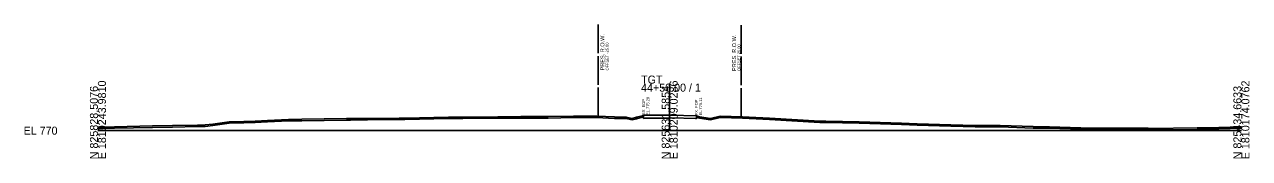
# Model space of a CAD drawing. Extents: x -26 to 1855242, y -29 to 826069.
# Drawn here: x -25.7 to 402.8, y 12490.3 to 12537 of the extents above; entities that cross this region are included whole.
import ezdxf

# ---------------------------------------------------------------- set-up
doc = ezdxf.new("R2010")
doc.units = 0
for name, color, linetype in [('DESIGN - SHEET - Light Grid', 7, 'Continuous'), ('SURVEY - AERIAL SURVEY - Mapping Setup - MAPPING LIMITS', 7, 'Continuous'), ('SURVEY - AERIAL SURVEY - Obscured Area', 7, 'Continuous'), ('SURVEY - AERIAL SURVEY - Out of collection Boundary Points', 7, 'Continuous'), ('SURVEY - AERIAL SURVEY - Skipped Points', 7, 'Continuous'), ('SURVEY - PROPERTY - ROW Lines', 7, 'Continuous'), ('SURVEY - PROPERTY - ROW Lines Text', 7, 'Continuous')]:
    doc.layers.add(name, color=color, linetype=linetype)

msp = doc.modelspace()

# ---------------------------------------------------------------- linework, layer by layer
at = {"layer": 'DESIGN - SHEET - Light Grid'}
for p, q in [((200, 12500), (200, 12516.4)), ((0, 12500), (200, 12500)), ((200, 12500), (400, 12500))]:
    msp.add_line(p, q, dxfattribs=at)
at = {"layer": 'SURVEY - AERIAL SURVEY - Mapping Setup - MAPPING LIMITS'}
msp.add_lwpolyline([(0, 12501.24), (1.85, 12501.26), (5.76, 12501.36), (19.1, 12501.64), (26.07, 12501.75), (34.83, 12501.92), (37.5, 12501.99), (40.15, 12502.31), (45.86, 12503.08), (50.98, 12503.21), (55.05, 12503.33), (59.36, 12503.52), (66.68, 12503.92), (71.29, 12503.96), (86.96, 12504.19), (88.31, 12504.2), (94.31, 12504.26), (105.36, 12504.35), (107.32, 12504.38), (122.61, 12504.69), (127.63, 12504.73), (139.86, 12504.82), (147.94, 12504.88), (157.44, 12504.9), (166.36, 12505.1), (174.49, 12505.03), (180.67, 12504.77), (184.31, 12504.75), (184.8, 12504.75), (185.2, 12504.64), (186.84, 12504.24), (188.39, 12504.67), (190.33, 12505.16), (190.88, 12505.29), (191.32, 12505.35), (200.2, 12505.36), (200.68, 12505.45), (209.19, 12505.21), (209.35, 12505.11), (210.4, 12504.86), (214.26, 12504.29), (217.72, 12505.06), (225.47, 12504.8), (234.97, 12504.39), (252.57, 12503.36), (252.88, 12503.35), (253.24, 12503.33), (254.59, 12503.3), (266.24, 12503.09), (281.09, 12502.64), (286.56, 12502.43), (298.34, 12502.03), (306.87, 12501.81), (315.59, 12501.82), (327.18, 12501.39), (332.84, 12501.33), (347.5, 12500.88), (364.73, 12500.81), (367.34, 12500.81), (367.81, 12500.8), (384.59, 12500.93), (388.12, 12501), (400, 12501.38)], dxfattribs=at)
at = {"layer": 'SURVEY - AERIAL SURVEY - Obscured Area'}
for p, q in [((157.44, 12504.4), (166.36, 12504.6)), ((166.36, 12504.6), (174.49, 12504.53)), ((188.39, 12504.17), (190.33, 12504.66)), ((190.33, 12504.66), (190.88, 12504.79)), ((190.88, 12504.79), (190.88, 12505.29)), ((209.35, 12504.61), (209.35, 12505.11)), ((209.35, 12504.61), (210.4, 12504.36)), ((0, 12500.74), (1.85, 12500.76)), ((1.85, 12500.76), (5.76, 12500.86)), ((5.76, 12500.86), (19.1, 12501.14)), ((19.1, 12501.14), (26.07, 12501.25)), ((26.07, 12501.25), (34.83, 12501.42)), ((34.83, 12501.42), (37.5, 12501.49)), ((37.5, 12501.49), (40.15, 12501.81)), ((40.15, 12501.81), (45.86, 12502.58)), ((45.86, 12502.58), (50.98, 12502.71)), ((50.98, 12502.71), (55.05, 12502.83)), ((55.05, 12502.83), (59.36, 12503.02)), ((59.36, 12503.02), (66.68, 12503.42)), ((66.68, 12503.42), (71.29, 12503.46)), ((71.29, 12503.46), (86.96, 12503.69)), ((86.96, 12503.69), (88.31, 12503.7)), ((88.31, 12503.7), (94.31, 12503.76)), ((94.31, 12503.76), (105.36, 12503.85)), ((105.36, 12503.85), (107.32, 12503.88)), ((107.32, 12503.88), (122.61, 12504.19)), ((122.61, 12504.19), (127.63, 12504.23)), ((127.63, 12504.23), (139.86, 12504.32)), ((139.86, 12504.32), (147.94, 12504.38)), ((147.94, 12504.38), (157.44, 12504.4)), ((174.49, 12504.53), (180.67, 12504.27)), ((180.67, 12504.27), (184.31, 12504.25)), ((184.31, 12504.25), (184.8, 12504.25)), ((184.8, 12504.25), (185.2, 12504.14)), ((185.2, 12504.14), (186.84, 12503.74)), ((186.84, 12503.74), (188.39, 12504.17)), ((210.4, 12504.36), (214.26, 12503.79)), ((214.26, 12503.79), (217.72, 12504.56)), ((217.72, 12504.56), (225.47, 12504.3)), ((225.47, 12504.3), (234.97, 12503.89)), ((234.97, 12503.89), (252.57, 12502.86)), ((252.57, 12502.86), (252.88, 12502.85)), ((252.88, 12502.85), (253.24, 12502.83)), ((253.24, 12502.83), (254.59, 12502.8)), ((254.59, 12502.8), (266.24, 12502.59)), ((266.24, 12502.59), (281.09, 12502.14)), ((281.09, 12502.14), (286.56, 12501.93)), ((286.56, 12501.93), (298.34, 12501.53)), ((298.34, 12501.53), (306.87, 12501.31)), ((306.87, 12501.31), (315.59, 12501.32)), ((315.59, 12501.32), (327.18, 12500.89)), ((327.18, 12500.89), (332.84, 12500.83)), ((332.84, 12500.83), (347.5, 12500.38)), ((347.5, 12500.38), (364.73, 12500.31)), ((364.73, 12500.31), (367.34, 12500.31)), ((367.34, 12500.31), (367.81, 12500.3)), ((367.81, 12500.3), (384.59, 12500.43)), ((384.59, 12500.43), (388.12, 12500.5)), ((388.12, 12500.5), (400, 12500.88))]:
    msp.add_line(p, q, dxfattribs=at)
at = {"layer": 'SURVEY - AERIAL SURVEY - Out of collection Boundary Points'}
for p, q in [((190.88, 12504.29), (190.88, 12505.29)), ((209.35, 12505.11), (209.35, 12504.11)), ((190.88, 12504.29), (191.32, 12504.35)), ((191.32, 12504.35), (200.2, 12504.36)), ((200.2, 12504.36), (200.68, 12504.45)), ((200.68, 12504.45), (209.19, 12504.21)), ((209.19, 12504.21), (209.35, 12504.11))]:
    msp.add_line(p, q, dxfattribs=at)
at = {"layer": 'SURVEY - PROPERTY - ROW Lines'}
for p, q in [((175, 12527), (175, 12537)), ((225, 12526.82), (225, 12536.82)), ((175, 12516), (175, 12526)), ((225, 12515.82), (225, 12525.82)), ((175, 12505), (175, 12515)), ((225, 12504.82), (225, 12514.82))]:
    msp.add_line(p, q, dxfattribs=at)

# ---------------------------------------------------------------- texts
at = {"layer": 'DESIGN - SHEET - Light Grid'}
for s, p in [('TGT', (190, 12516.4)), ('44+50.00 / 1', (190, 12513.6)), ('EL 770', (-26, 12498.6))]:
    msp.add_text(s, height=2.8, dxfattribs=at).set_placement(p)
for s, p in [('N 825828.5076', (0, 12490)), ('E 1810243.9810', (2.8, 12490)), ('N 825631.5854', (200, 12490)), ('E 1810209.0286', (202.8, 12490)), ('N 825434.6633', (400, 12490)), ('E 1810174.0762', (402.8, 12490))]:
    msp.add_text(s, height=2.8, rotation=90, dxfattribs=at).set_placement(p)
at = {"layer": 'SURVEY - AERIAL SURVEY - Skipped Points'}
for s, p in [('EX. EOP', (191.38, 12505.49)), ('EL.775.29', (192.88, 12505.49)), ('EX. EOP', (209.85, 12505.31)), ('EL.775.11', (211.35, 12505.31))]:
    msp.add_text(s, height=1, rotation=90, dxfattribs=at).set_placement(p)
at = {"layer": 'SURVEY - PROPERTY - ROW Lines Text'}
for s, height, p in [('PRES. R.O.W.', 1.4, (177.15, 12521)), ('OFFSET -25.00', 1, (178.65, 12521)), ('PRES. R.O.W.', 1.4, (223.25, 12520.82)), ('OFFSET 25.00', 1, (224.75, 12520.82))]:
    msp.add_text(s, height=height, rotation=90, dxfattribs=at).set_placement(p)

doc.saveas('drawing.dxf')
